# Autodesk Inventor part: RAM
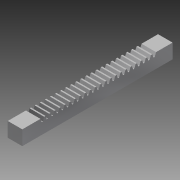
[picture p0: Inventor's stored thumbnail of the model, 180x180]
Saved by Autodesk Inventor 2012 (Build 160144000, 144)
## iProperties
Shininess: 64.0
Length Units: 11272
Angle Units: 11279
Time Units: 11290
Mass Units: 11286
Length Display Precision: 3
Angle Display Precision: 2
Compacted: True
Part Number: RAM
Document SubType Name: Modeling
Created: 2003-11
Designer: Autodesk, Inc.
Manufacturer: Standard
Standards Organization: Custom
Mass: 509.763 g
Surface Area: 178.528 cm^2
Volume: 65.0208 cm^3
Density: 7.84 g/cm^3
Material: Steel, High Strength Low Alloy
Density: 0.0
Volumn: 0.0
Area: 0.0
PropertySet Name: Model Information
Control State: 0
Master: False
Checked Out: False
Author: Autodesk, Inc.
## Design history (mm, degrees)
sketch "Sketch1"
  geometry: L1 (0, 0)-(19.05, 0); L2 (19.05, 0)-(19.05, 19.05); L3 (19.05, 19.05)-(0, 19.05); L4 (0, 19.05)-(0, 0)
  constraints: 8 end point, 2 parallel, 1 horizontal, 1 perpendicular
  dimensions: "d0" = 19.05 distance of L1.start L1.end; "d1" = 19.05 distance of L1.end L2.end
extrude "Extrusion1" new body sketch "Sketch1" distance "d2" = 196.85; taper "d3" = 0 deg
sketch "Sketch2"
  geometry: L1 (0, 0)-(0, 19.05) reference; L2 (0, 19.05)-(-196.85, 19.05) reference; L3 (-196.85, 19.05)-(-196.85, 0) reference; L4 (0, 0)-(-196.85, 0) reference; L5 (-168.185, 19.05)-(-166.4, 19.05); L6 (-166.4, 19.05)-(-164.739, 14.486); L7 (-168.185, 19.05)-(-169.846, 14.486); L8 (-167.293, 19.05)-(-167.293, 27.541); L9 (-130.145, 19.823)-(-130.145, 4.561); L10 (-173.431, 16.934)-(-94.815, 16.934); L11 (-163.197, 14.486)-(-161.535, 19.05); L12 (-161.535, 19.05)-(-159.751, 19.05); L13 (-159.751, 19.05)-(-158.089, 14.486); L14 (-164.739, 14.486)-(-163.197, 14.486); L15 (-158.089, 14.486)-(-24.993, 14.486); L16 (-160.643, 19.05)-(-160.643, 25.268); L17 (-169.846, 14.486)-(-171.389, 14.486); L18 (-171.389, 14.486)-(-173.05, 19.05); L19 (-156.542, 14.486)-(-154.881, 19.05); L20 (-154.881, 19.05)-(-153.096, 19.05); L21 (-153.096, 19.05)-(-151.435, 14.486); L22 (-149.887, 14.486)-(-148.226, 19.05); L23 (-148.226, 19.05)-(-146.441, 19.05); L24 (-146.441, 19.05)-(-144.78, 14.486); L25 (-143.232, 14.486)-(-141.571, 19.05); L26 (-141.571, 19.05)-(-139.786, 19.05); L27 (-139.786, 19.05)-(-138.125, 14.486); L28 (-136.578, 14.486)-(-134.916, 19.05); L29 (-134.916, 19.05)-(-133.132, 19.05); L30 (-133.132, 19.05)-(-131.47, 14.486); L31 (-129.923, 14.486)-(-128.261, 19.05); L32 (-128.261, 19.05)-(-126.477, 19.05); L33 (-126.477, 19.05)-(-124.815, 14.486); L34 (-123.268, 14.486)-(-121.607, 19.05); L35 (-121.607, 19.05)-(-119.822, 19.05); L36 (-119.822, 19.05)-(-118.161, 14.486); L37 (-116.613, 14.486)-(-114.952, 19.05); L38 (-114.952, 19.05)-(-113.167, 19.05); L39 (-113.167, 19.05)-(-111.506, 14.486); L40 (-109.958, 14.486)-(-108.297, 19.05); L41 (-108.297, 19.05)-(-106.512, 19.05); L42 (-106.512, 19.05)-(-104.851, 14.486); L43 (-103.304, 14.486)-(-101.642, 19.05); L44 (-101.642, 19.05)-(-99.858, 19.05); L45 (-99.858, 19.05)-(-98.196, 14.486); L46 (-96.649, 14.486)-(-94.987, 19.05); L47 (-94.987, 19.05)-(-93.203, 19.05); L48 (-93.203, 19.05)-(-91.541, 14.486); L49 (-89.994, 14.486)-(-88.333, 19.05); L50 (-88.333, 19.05)-(-86.548, 19.05); L51 (-86.548, 19.05)-(-84.887, 14.486); L52 (-83.339, 14.486)-(-81.678, 19.05); L53 (-81.678, 19.05)-(-79.893, 19.05); L54 (-79.893, 19.05)-(-78.232, 14.486); L55 (-76.684, 14.486)-(-75.023, 19.05); L56 (-75.023, 19.05)-(-73.238, 19.05); L57 (-73.238, 19.05)-(-71.577, 14.486); L58 (-70.03, 14.486)-(-68.368, 19.05); L59 (-68.368, 19.05)-(-66.584, 19.05); L60 (-66.584, 19.05)-(-64.922, 14.486); L61 (-63.375, 14.486)-(-61.713, 19.05); L62 (-61.713, 19.05)-(-59.929, 19.05); L63 (-59.929, 19.05)-(-58.267, 14.486); L64 (-56.72, 14.486)-(-55.059, 19.05)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; 65 further points
  constraints: 201 end point, 53 point on line, 27 collinear, 10 parallel, 3 perpendicular, 2 midpoint, 1 coincident, 1 horizontal, 200 other
  dimensions: "d5" = 2.11582 distance between parallel lines of L10 L5; "d6" = 20 deg angle of L8 L7; "d7" = 20 deg angle of L6 L8; "d11" = 6.64972 distance between parallel lines of L16 L8; "d12" = 3.32486 distance of point (-165.63, 16.934) point (-168.955, 16.934); "d13" = 3.32486 distance of point (-158.981, 16.934) point (-162.306, 16.934) (= d12); "d14" = 3.32486 distance of point (-168.955, 16.934) point (-172.28, 16.934) (= d12); "d15" = 23.7998 distance from line of L3 L18.end; "d16" = 2.44856 distance between parallel lines of L17 L10; "d19" = 6.6548 distance of L11.start L19.start
extrude "Extrusion2" sketch "Sketch2" stored distance "d24" = 25.4; taper "d25" = 0 deg
sketch "Sketch5"
  geometry: L1 (126.82, 14.486)-(128.482, 19.05) reference; L2 (125.273, 14.486)-(126.82, 14.486) reference; L3 (123.612, 19.05)-(125.273, 14.486) reference; L4 (123.612, 19.05)-(121.827, 19.05) reference; L5 (120.166, 14.486)-(121.827, 19.05) reference; L6 (118.618, 14.486)-(120.166, 14.486) reference; L7 (116.957, 19.05)-(118.618, 14.486) reference; L8 (116.957, 19.05)-(115.172, 19.05) reference; L9 (113.511, 14.486)-(115.172, 19.05) reference; L10 (111.963, 14.486)-(113.511, 14.486) reference; L11 (110.302, 19.05)-(111.963, 14.486) reference; L12 (110.302, 19.05)-(108.517, 19.05) reference; L13 (106.856, 14.486)-(108.517, 19.05) reference; L14 (105.309, 14.486)-(106.856, 14.486) reference; L15 (103.647, 19.05)-(105.309, 14.486) reference; L16 (103.647, 19.05)-(101.863, 19.05) reference; L17 (100.201, 14.486)-(101.863, 19.05) reference; L18 (98.654, 14.486)-(100.201, 14.486) reference; L19 (96.992, 19.05)-(98.654, 14.486) reference; L20 (96.992, 19.05)-(95.208, 19.05) reference; L21 (93.546, 14.486)-(95.208, 19.05) reference; L22 (91.999, 14.486)-(93.546, 14.486) reference; L23 (90.338, 19.05)-(91.999, 14.486) reference; L24 (90.338, 19.05)-(88.553, 19.05) reference; L25 (86.892, 14.486)-(88.553, 19.05) reference; L26 (85.344, 14.486)-(86.892, 14.486) reference; L27 (83.683, 19.05)-(85.344, 14.486) reference; L28 (83.683, 19.05)-(81.898, 19.05) reference; L29 (80.237, 14.486)-(81.898, 19.05) reference; L30 (78.689, 14.486)-(80.237, 14.486) reference; L31 (77.028, 19.05)-(78.689, 14.486) reference; L32 (77.028, 19.05)-(75.243, 19.05) reference; L33 (73.582, 14.486)-(75.243, 19.05) reference; L34 (72.035, 14.486)-(73.582, 14.486) reference; L35 (70.373, 19.05)-(72.035, 14.486) reference; L36 (70.373, 19.05)-(68.589, 19.05) reference; L37 (66.927, 14.486)-(68.589, 19.05) reference; L38 (65.38, 14.486)-(66.927, 14.486) reference; L39 (63.718, 19.05)-(65.38, 14.486) reference; L40 (63.718, 19.05)-(61.934, 19.05) reference; L41 (60.272, 14.486)-(61.934, 19.05) reference; L42 (58.725, 14.486)-(60.272, 14.486) reference; L43 (57.064, 19.05)-(58.725, 14.486) reference; L44 (57.064, 19.05)-(55.279, 19.05) reference; L45 (53.618, 14.486)-(55.279, 19.05) reference; L46 (52.07, 14.486)-(53.618, 14.486) reference; L47 (50.409, 19.05)-(52.07, 14.486) reference; L48 (50.409, 19.05)-(48.624, 19.05) reference; L49 (46.963, 14.486)-(48.624, 19.05) reference; L50 (45.415, 14.486)-(46.963, 14.486) reference; L51 (43.754, 19.05)-(45.415, 14.486) reference; L52 (43.754, 19.05)-(41.969, 19.05) reference; L53 (40.308, 14.486)-(41.969, 19.05) reference; L54 (38.761, 14.486)-(40.308, 14.486) reference; L55 (37.099, 19.05)-(38.761, 14.486) reference; L56 (37.099, 19.05)-(35.315, 19.05) reference; L57 (33.653, 14.486)-(35.315, 19.05) reference; L58 (32.111, 14.486)-(33.653, 14.486) reference; L59 (30.45, 19.05)-(32.111, 14.486) reference; L60 (30.45, 19.05)-(28.665, 19.05) reference; L61 (27.004, 14.486)-(28.665, 19.05) reference; L62 (25.461, 14.486)-(27.004, 14.486) reference; L63 (23.8, 19.05)-(25.461, 14.486) reference; L64 (23.8, 19.05)-(0, 19.05) reference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
  constraints: 10 end point, 3 parallel, 2 collinear, 2 point on line
  dimensions: "d26" = 1.5494 distance of L94.end L95.end; "d27" = 1.905 distance of L68.end L93.end
extrude "Extrusion3" cut sketch "Sketch5" distance "d28" = 25.4; taper "d29" = 0 deg
body "Solid1"
node "Projected Loop1"
node "Projected Loop4"
other parameters: "d22" = 25.4
